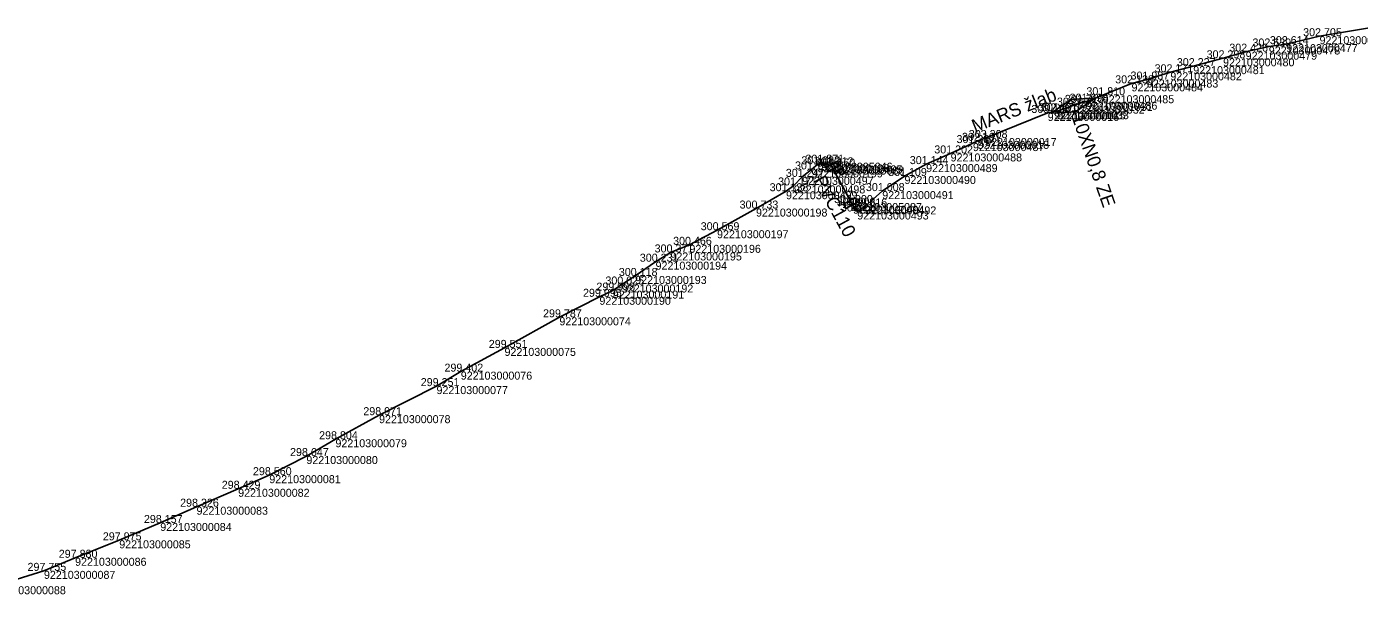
# Model space of a CAD drawing. Extents: x -771047 to -756200, y -1053876 to -1046520.
# Drawn here: x -766394.6 to -766194.7, y -1051866.7 to -1051781.5 of the extents above; entities that cross this region are included whole.
import ezdxf

# ---------------------------------------------------------------- set-up
doc = ezdxf.new("R2010")
doc.units = 0
for name, color, linetype in [('Vrstva 32', 7, 'Continuous'), ('Vrstva 33', 7, 'Continuous'), ('Vrstva 60', 7, 'Continuous'), ('Vrstva 61', 7, 'Continuous')]:
    doc.layers.add(name, color=color, linetype=linetype)

msp = doc.modelspace()

# ---------------------------------------------------------------- linework, layer by layer
at = {"layer": 'Vrstva 32'}
for points in [[(-766192, -1051781.52), (-766200.7, -1051782.96), (-766205.7, -1051784.15), (-766208.31, -1051784.5), (-766211.78, -1051785.28), (-766215.17, -1051786.27), (-766219.64, -1051787.45), (-766223.07, -1051788.37), (-766226.59, -1051789.46), (-766228.89, -1051790.03), (-766233.21, -1051791.81), (-766235.73, -1051792.78), (-766236.43, -1051792.96), (-766237.63, -1051793.37), (-766240.01, -1051794.2), (-766240.48, -1051794.23)], [(-766240.94, -1051794.52), (-766237.96, -1051792.43), (-766234.32, -1051792.23), (-766237.3, -1051794.32), (-766240.94, -1051794.52)], [(-766240.48, -1051794.23), (-766241.46, -1051794.47), (-766250.84, -1051798.23), (-766251.96, -1051798.65), (-766252.67, -1051798.99)], [(-766252.67, -1051798.99), (-766256.02, -1051800.54), (-766259.69, -1051802.14), (-766262.94, -1051803.93), (-766266.27, -1051806.19), (-766268.88, -1051808.49), (-766270.02, -1051809.25), (-766270.65, -1051808.38), (-766273.95, -1051802.33), (-766275.43, -1051801.93), (-766275.95, -1051802.17), (-766276.9, -1051802.94), (-766278.28, -1051804.06), (-766279.53, -1051805.34), (-766280.7, -1051806.21), (-766285.2, -1051808.81), (-766291.04, -1051812.06), (-766295.18, -1051814.25), (-766298.04, -1051815.39), (-766300.26, -1051816.78), (-766303.31, -1051818.92), (-766305.32, -1051820.2), (-766306.68, -1051821.12), (-766308.68, -1051822.04), (-766314.68, -1051825.12), (-766322.91, -1051829.71), (-766329.47, -1051833.27), (-766333.11, -1051835.44), (-766341.72, -1051839.8), (-766348.26, -1051843.41), (-766352.62, -1051845.93), (-766358.18, -1051848.8), (-766362.85, -1051850.84), (-766369.09, -1051853.53), (-766374.53, -1051855.97), (-766380.68, -1051858.57), (-766387.3, -1051861.19), (-766391.97, -1051863.15), (-766399.4, -1051865.46)]]:
    msp.add_lwpolyline(points, dxfattribs=at)
at = {"layer": 'Vrstva 33'}
for points in [[(-766251.96, -1051798.65), (-766250.84, -1051798.23), (-766241.46, -1051794.47), (-766240.48, -1051794.23)], [(-766270.65, -1051808.38), (-766273.95, -1051802.33)], [(-766273.46, -1051803.41), (-766272.35, -1051802.81)], [(-766272.65, -1051803.57), (-766272.9, -1051803.11)], [(-766272.35, -1051802.81), (-766272.1, -1051803.27)], [(-766272.1, -1051803.27), (-766272.08, -1051803.43), (-766272.2, -1051803.63), (-766272.3, -1051803.68), (-766272.53, -1051803.68), (-766272.65, -1051803.57)], [(-766270.82, -1051808.88), (-766269.71, -1051808.28)], [(-766270.01, -1051809.04), (-766270.26, -1051808.58)], [(-766269.46, -1051808.74), (-766269.44, -1051808.9), (-766269.56, -1051809.1), (-766269.66, -1051809.15), (-766269.89, -1051809.15), (-766270.01, -1051809.04)], [(-766269.71, -1051808.28), (-766269.46, -1051808.74)]]:
    msp.add_lwpolyline(points, dxfattribs=at)
for points in [[(-766272.96, -1051801.7), (-766272.61, -1051802.36), (-766274.38, -1051803.32), (-766274.73, -1051802.66)], [(-766270.32, -1051807.17), (-766269.97, -1051807.83), (-766271.74, -1051808.79), (-766272.09, -1051808.13)]]:
    msp.add_lwpolyline(points, close=True, dxfattribs=at)
at = {"layer": 'Vrstva 60'}
for p, q in [((-766200.7, -1051782.96), (-766200.7, -1051782.96)), ((-766208.31, -1051784.5), (-766208.31, -1051784.5)), ((-766205.7, -1051784.15), (-766205.7, -1051784.15)), ((-766215.17, -1051786.27), (-766215.17, -1051786.27)), ((-766211.78, -1051785.28), (-766211.78, -1051785.28)), ((-766223.07, -1051788.37), (-766223.07, -1051788.37)), ((-766219.64, -1051787.45), (-766219.64, -1051787.45)), ((-766228.89, -1051790.03), (-766228.89, -1051790.03)), ((-766226.59, -1051789.46), (-766226.59, -1051789.46)), ((-766236.43, -1051792.96), (-766236.43, -1051792.96)), ((-766235.73, -1051792.78), (-766235.73, -1051792.78)), ((-766233.21, -1051791.81), (-766233.21, -1051791.81)), ((-766241.46, -1051794.47), (-766241.46, -1051794.47)), ((-766240.48, -1051794.23), (-766240.48, -1051794.23)), ((-766240.01, -1051794.2), (-766240.01, -1051794.2)), ((-766237.63, -1051793.37), (-766237.63, -1051793.37)), ((-766252.67, -1051798.99), (-766252.67, -1051798.99)), ((-766251.96, -1051798.65), (-766251.96, -1051798.65)), ((-766250.84, -1051798.23), (-766250.84, -1051798.23)), ((-766256.02, -1051800.54), (-766256.02, -1051800.54)), ((-766276.9, -1051802.94), (-766276.9, -1051802.94)), ((-766275.95, -1051802.17), (-766275.95, -1051802.17)), ((-766275.43, -1051801.93), (-766275.43, -1051801.93)), ((-766273.95, -1051802.33), (-766273.95, -1051802.33)), ((-766273.67, -1051802.51), (-766273.67, -1051802.51)), ((-766259.69, -1051802.14), (-766259.69, -1051802.14)), ((-766278.28, -1051804.06), (-766278.28, -1051804.06)), ((-766262.94, -1051803.93), (-766262.94, -1051803.93)), ((-766280.7, -1051806.21), (-766280.7, -1051806.21)), ((-766279.53, -1051805.34), (-766279.53, -1051805.34)), ((-766266.27, -1051806.19), (-766266.27, -1051806.19)), ((-766285.2, -1051808.81), (-766285.2, -1051808.81)), ((-766271.03, -1051807.98), (-766271.03, -1051807.98)), ((-766270.65, -1051808.38), (-766270.65, -1051808.38)), ((-766268.88, -1051808.49), (-766268.88, -1051808.49)), ((-766270.02, -1051809.25), (-766270.02, -1051809.25)), ((-766291.04, -1051812.06), (-766291.04, -1051812.06)), ((-766295.18, -1051814.25), (-766295.18, -1051814.25)), ((-766300.26, -1051816.78), (-766300.26, -1051816.78)), ((-766298.04, -1051815.39), (-766298.04, -1051815.39)), ((-766303.31, -1051818.92), (-766303.31, -1051818.92)), ((-766306.68, -1051821.12), (-766306.68, -1051821.12)), ((-766305.32, -1051820.2), (-766305.32, -1051820.2)), ((-766308.68, -1051822.04), (-766308.68, -1051822.04)), ((-766314.68, -1051825.12), (-766314.68, -1051825.12)), ((-766322.91, -1051829.71), (-766322.91, -1051829.71)), ((-766329.47, -1051833.27), (-766329.47, -1051833.27)), ((-766333.11, -1051835.44), (-766333.11, -1051835.44)), ((-766341.72, -1051839.8), (-766341.72, -1051839.8)), ((-766348.26, -1051843.41), (-766348.26, -1051843.41)), ((-766352.62, -1051845.93), (-766352.62, -1051845.93)), ((-766358.18, -1051848.8), (-766358.18, -1051848.8)), ((-766362.85, -1051850.84), (-766362.85, -1051850.84)), ((-766369.09, -1051853.53), (-766369.09, -1051853.53)), ((-766374.53, -1051855.97), (-766374.53, -1051855.97)), ((-766380.68, -1051858.57), (-766380.68, -1051858.57)), ((-766387.3, -1051861.19), (-766387.3, -1051861.19)), ((-766391.97, -1051863.15), (-766391.97, -1051863.15))]:
    msp.add_line(p, q, dxfattribs=at)

# ---------------------------------------------------------------- texts
at = {"layer": 'Vrstva 32'}
msp.add_text('10XN0,8 ZE', height=2, rotation=289.1333, dxfattribs=at).set_placement((-766237.9, -1051795.05))
at = {"layer": 'Vrstva 33'}
for s, rotation, p in [('MARS žlab', 21.8235, (-766252.36, -1051797.47)), ('PVC110', 298.5514, (-766276.63, -1051804.55))]:
    msp.add_text(s, height=2, rotation=rotation, dxfattribs=at).set_placement(p)
at = {"layer": 'Vrstva 60'}
for s, p in [('922103000476', (-766200.7, -1051784.16)), ('922103000478', (-766208.31, -1051785.7)), ('922103000477', (-766205.7, -1051785.35)), ('922103000480', (-766215.17, -1051787.47)), ('922103000479', (-766211.78, -1051786.48)), ('922103000482', (-766223.07, -1051789.57)), ('922103000481', (-766219.64, -1051788.65)), ('922103000484', (-766228.89, -1051791.23)), ('922103000483', (-766226.59, -1051790.66)), ('922103001031', (-766236.43, -1051794.16)), ('922103000486', (-766235.73, -1051793.98)), ('922103000485', (-766233.21, -1051793.01)), ('922103000016', (-766241.46, -1051795.67)), ('922103000015', (-766240.48, -1051795.43)), ('922103001033', (-766240.01, -1051795.4)), ('922103001032', (-766237.63, -1051794.57)), ('922103000487', (-766252.67, -1051800.19)), ('922103000018', (-766251.96, -1051799.85)), ('922103000017', (-766250.84, -1051799.43)), ('922103000488', (-766256.02, -1051801.74)), ('922103000199', (-766276.9, -1051804.14)), ('922103000496', (-766275.95, -1051803.37)), ('922103005046', (-766275.43, -1051803.13)), ('922103000495', (-766273.95, -1051803.53)), ('922103005088', (-766273.67, -1051803.71)), ('922103000489', (-766259.69, -1051803.34)), ('922103000497', (-766278.28, -1051805.26)), ('922103000490', (-766262.94, -1051805.13)), ('922103000499', (-766280.7, -1051807.41)), ('922103000498', (-766279.53, -1051806.54)), ('922103000491', (-766266.27, -1051807.39)), ('922103000198', (-766285.2, -1051810.01)), ('922103005087', (-766271.03, -1051809.18)), ('922103000494', (-766270.65, -1051809.58)), ('922103000492', (-766268.88, -1051809.69)), ('922103000493', (-766270.02, -1051810.45)), ('922103000197', (-766291.04, -1051813.26)), ('922103000196', (-766295.18, -1051815.45)), ('922103000194', (-766300.26, -1051817.98)), ('922103000195', (-766298.04, -1051816.59)), ('922103000193', (-766303.31, -1051820.12)), ('922103000191', (-766306.68, -1051822.32)), ('922103000192', (-766305.32, -1051821.4)), ('922103000190', (-766308.68, -1051823.24)), ('922103000074', (-766314.68, -1051826.32)), ('922103000075', (-766322.91, -1051830.91)), ('922103000076', (-766329.47, -1051834.47)), ('922103000077', (-766333.11, -1051836.64)), ('922103000078', (-766341.72, -1051841)), ('922103000079', (-766348.26, -1051844.61)), ('922103000080', (-766352.62, -1051847.13)), ('922103000081', (-766358.18, -1051850)), ('922103000082', (-766362.85, -1051852.04)), ('922103000083', (-766369.09, -1051854.73)), ('922103000084', (-766374.53, -1051857.17)), ('922103000085', (-766380.68, -1051859.77)), ('922103000086', (-766387.3, -1051862.39)), ('922103000087', (-766391.97, -1051864.35)), ('922103000088', (-766399.4, -1051866.66))]:
    msp.add_text(s, height=1.2, dxfattribs=at).set_placement(p)
at = {"layer": 'Vrstva 61'}
for s, p in [('302.614', (-766208.15, -1051784.15)), ('302.705', (-766203.16, -1051782.96)), ('302.298', (-766217.63, -1051786.27)), ('302.426', (-766214.23, -1051785.28)), ('302.639', (-766210.76, -1051784.5)), ('302.171', (-766225.43, -1051788.37)), ('302.227', (-766222.1, -1051787.45)), ('302.138', (-766231.34, -1051790.03)), ('301.987', (-766229.04, -1051789.46)), ('301.810', (-766235.66, -1051791.81)), ('302.431', (-766242.83, -1051794.23)), ('301.670', (-766242.46, -1051794.2)), ('301.672', (-766240.08, -1051793.37)), ('301.710', (-766238.88, -1051792.96)), ('301.698', (-766238.18, -1051792.78)), ('303.426', (-766243.91, -1051794.47)), ('303.308', (-766253.29, -1051798.23)), ('301.387', (-766255.13, -1051798.99)), ('302.161', (-766254.32, -1051798.65)), ('301.082', (-766278.4, -1051802.17)), ('301.871', (-766277.79, -1051801.93)), ('301.212', (-766276.39, -1051802.33)), ('301.144', (-766262.14, -1051802.14)), ('301.202', (-766258.47, -1051800.54)), ('301.247', (-766280.73, -1051804.06)), ('301.143', (-766279.35, -1051802.94)), ('302.160', (-766276.12, -1051802.51)), ('301.109', (-766265.39, -1051803.93)), ('301.138', (-766283.15, -1051806.21)), ('301.171', (-766281.89, -1051805.34)), ('301.008', (-766268.72, -1051806.19)), ('301.900', (-766273.48, -1051807.98)), ('300.906', (-766273.1, -1051808.38)), ('300.733', (-766287.66, -1051808.81)), ('300.717', (-766272.47, -1051809.25)), ('300.816', (-766271.33, -1051808.49)), ('300.569', (-766293.49, -1051812.06)), ('300.466', (-766297.63, -1051814.25)), ('300.371', (-766300.4, -1051815.39)), ('300.231', (-766302.62, -1051816.78)), ('300.025', (-766307.78, -1051820.2)), ('300.118', (-766305.77, -1051818.92)), ('299.995', (-766311.14, -1051822.04)), ('299.998', (-766309.13, -1051821.12)), ('299.787', (-766317.13, -1051825.12)), ('299.551', (-766325.27, -1051829.71)), ('299.402', (-766331.91, -1051833.27)), ('299.251', (-766335.47, -1051835.44)), ('298.971', (-766344.08, -1051839.8)), ('298.804', (-766350.71, -1051843.41)), ('298.647', (-766355.07, -1051845.93)), ('298.560', (-766360.63, -1051848.8)), ('298.429', (-766365.31, -1051850.84)), ('298.326', (-766371.55, -1051853.53)), ('298.157', (-766376.98, -1051855.97)), ('297.975', (-766383.14, -1051858.57)), ('297.880', (-766389.75, -1051861.19)), ('297.755', (-766394.43, -1051863.15))]:
    msp.add_text(s, height=1.2, dxfattribs=at).set_placement(p)

doc.saveas('drawing.dxf')
